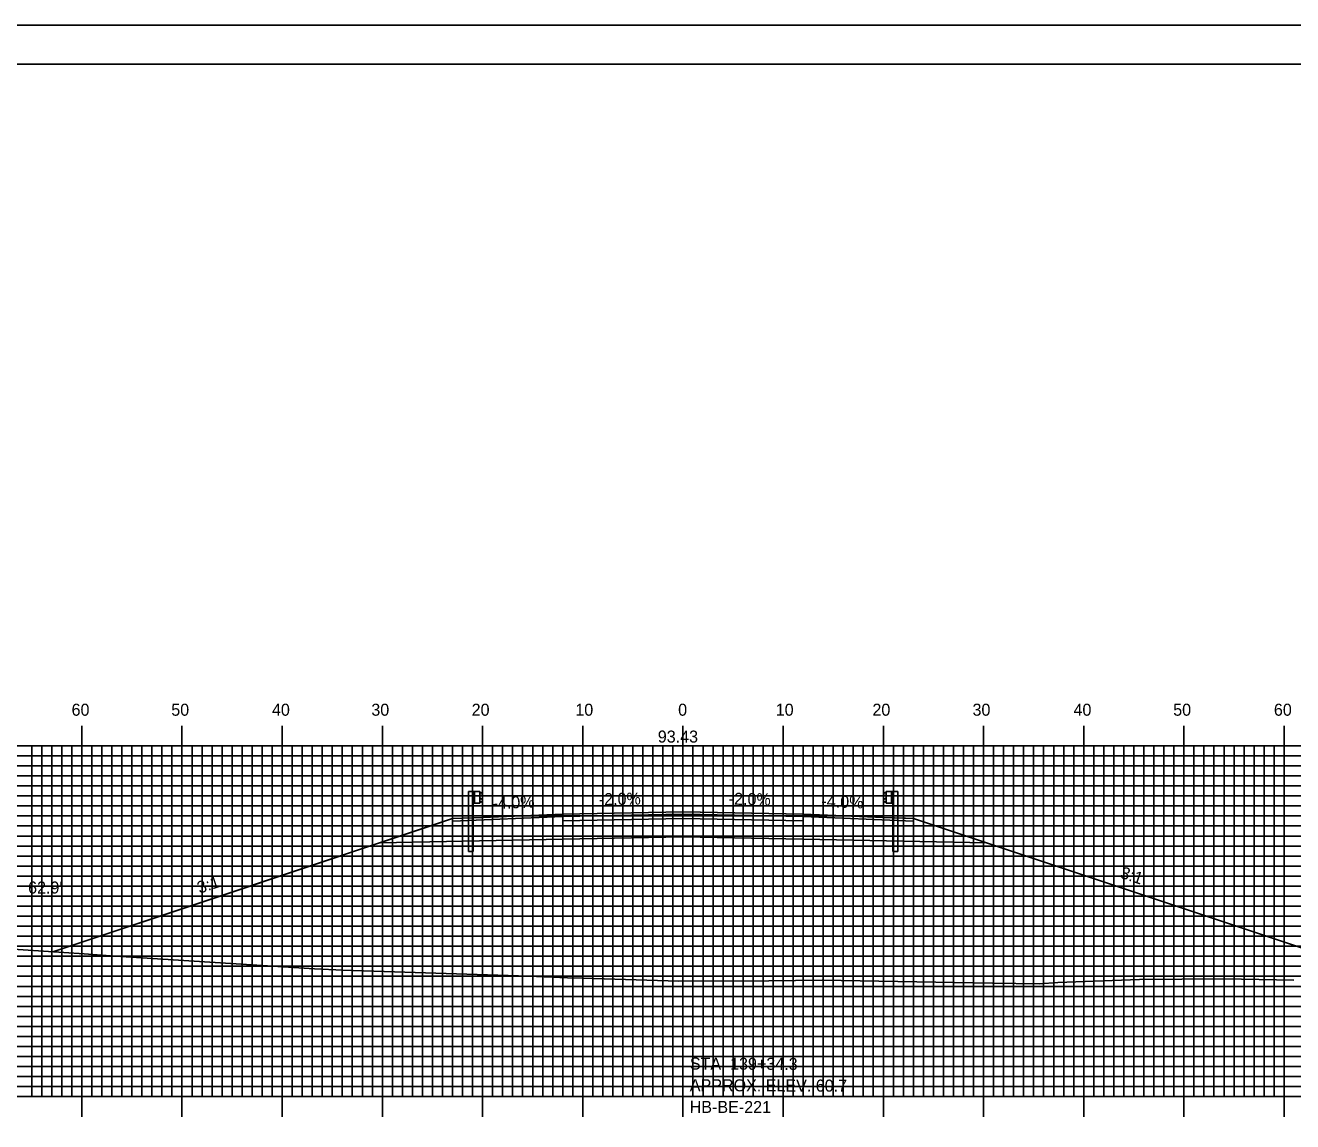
# Model space of a CAD drawing. Extents: x 1775957 to 1776301, y 442591 to 442811.
# Drawn here: x 1776057.6 to 1776184.1, y 442701.2 to 442810.5 of the extents above; entities that cross this region are included whole.
import ezdxf

# ---------------------------------------------------------------- set-up
doc = ezdxf.new("R2010")
doc.units = 0
for name, color, linetype in [('ANNOTATION', 7, 'Continuous'), ('BORDER', 7, 'Continuous'), ('BORING - NO REFUSAL', 7, 'Continuous'), ('D_Guardrail_Beam_Lt', 7, 'Continuous'), ('D_Guardrail_Beam_Rt', 7, 'Continuous'), ('D_Roadway_Centerline', 7, 'Continuous'), ('D_Roadway_Centerline_Text', 7, 'Continuous'), ('D_Roadway_Edge_Shoulder', 7, 'Continuous'), ('D_Roadway_Edge_TW', 7, 'Continuous'), ('D_Roadway_Pavement', 7, 'Continuous'), ('D_Roadway_SlopeLines', 7, 'Continuous'), ('D_Roadway_SubGrade', 7, 'Continuous'), ('D_Text_Standard', 7, 'Continuous'), ('H_V ANNOTATION', 7, 'Continuous'), ('MAJOR', 7, 'Continuous'), ('MINOR', 7, 'Continuous'), ('PLOT BOUNDARY', 7, 'Continuous'), ('S_Roadway_Centerline', 7, 'Continuous')]:
    doc.layers.add(name, color=color, linetype=linetype)

msp = doc.modelspace()

# ---------------------------------------------------------------- linework, layer by layer
at = {"layer": 'BORDER'}
msp.add_lwpolyline([(1775973.62, 442596.67), (1776293.62, 442596.67), (1776293.62, 442806.67), (1775973.62, 442806.67)], close=True, dxfattribs=at)
at = {"layer": 'D_Guardrail_Beam_Lt'}
for p, q in [((1776101.8, 442734.12), (1776101.8, 442728.12)), ((1776102.27, 442734.12), (1776101.8, 442734.12)), ((1776102.95, 442734.12), (1776102.27, 442734.12)), ((1776102.27, 442734.12), (1776102.27, 442732.95)), ((1776102.27, 442732.95), (1776102.95, 442732.95)), ((1776102.29, 442728.12), (1776102.29, 442732.95)), ((1776102.33, 442734.12), (1776102.33, 442732.95)), ((1776102.43, 442734.12), (1776102.43, 442732.95)), ((1776102.95, 442732.95), (1776102.95, 442734.12)), ((1776102.95, 442734.03), (1776103.03, 442734.02)), ((1776103.03, 442733.05), (1776102.95, 442733.03)), ((1776102.96, 442733.57), (1776102.96, 442733.5)), ((1776103.19, 442733.77), (1776102.99, 442733.63)), ((1776102.99, 442733.43), (1776103.19, 442733.3)), ((1776103.04, 442734.01), (1776103.19, 442733.91)), ((1776103.19, 442733.16), (1776103.04, 442733.06)), ((1776102.29, 442728.12), (1776101.8, 442728.12))]:
    msp.add_line(p, q, dxfattribs=at)
for centre, major_axis, start_param, end_param in [((1776103.04, 442733.57), (-0.0789, 0), 5.323254, 6.283185), ((1776103.04, 442733.5), (-0.0789, 0), 6.283185, 7.243116), ((1776103.02, 442733.98), (0.0417, 0), 0.959931, 1.376053), ((1776103.02, 442733.09), (0.0417, 0), 4.907132, 5.323254), ((1776103.14, 442733.84), (0.0877, 0), 5.323254, 7.243116), ((1776103.14, 442733.23), (0.0877, 0), 5.323254, 7.243116)]:
    msp.add_ellipse(centre, major_axis=major_axis, ratio=0.995501, start_param=start_param, end_param=end_param, dxfattribs=at)
at = {"layer": 'D_Guardrail_Beam_Rt'}
for p, q in [((1776143.41, 442734.01), (1776143.26, 442733.91)), ((1776143.26, 442733.77), (1776143.46, 442733.63)), ((1776143.46, 442733.43), (1776143.26, 442733.3)), ((1776143.26, 442733.16), (1776143.41, 442733.06)), ((1776143.5, 442734.03), (1776143.42, 442734.02)), ((1776143.42, 442733.05), (1776143.5, 442733.03)), ((1776143.49, 442733.57), (1776143.49, 442733.5)), ((1776143.5, 442734.12), (1776144.18, 442734.12)), ((1776143.5, 442732.95), (1776143.5, 442734.12)), ((1776144.18, 442732.95), (1776143.5, 442732.95)), ((1776144.02, 442734.12), (1776144.02, 442732.95)), ((1776144.12, 442734.12), (1776144.12, 442732.95)), ((1776144.16, 442728.12), (1776144.16, 442732.95)), ((1776144.18, 442734.12), (1776144.65, 442734.12)), ((1776144.18, 442734.12), (1776144.18, 442732.95)), ((1776144.65, 442734.12), (1776144.65, 442728.12)), ((1776144.16, 442728.12), (1776144.65, 442728.12))]:
    msp.add_line(p, q, dxfattribs=at)
for centre, major_axis, start_param, end_param in [((1776143.31, 442733.84), (-0.0877, 0), 5.323254, 7.243116), ((1776143.31, 442733.23), (-0.0877, 0), 5.323254, 7.243116), ((1776143.43, 442733.98), (-0.0417, 0), 4.907132, 5.323254), ((1776143.43, 442733.09), (-0.0417, 0), 0.959931, 1.376053), ((1776143.41, 442733.57), (0.0789, 0), 0, 0.959931), ((1776143.41, 442733.5), (0.0789, 0), 5.323254, 6.283185)]:
    msp.add_ellipse(centre, major_axis=major_axis, ratio=0.995501, start_param=start_param, end_param=end_param, dxfattribs=at)
at = {"layer": 'D_Roadway_Centerline'}
msp.add_lwpolyline([(1776060.32, 442718.11), (1776060.34, 442718.12), (1776077.43, 442723.81), (1776092.93, 442728.98), (1776092.95, 442728.99), (1776092.95, 442728.99), (1776097.86, 442730.63), (1776100.22, 442731.41), (1776103.22, 442731.53), (1776111.22, 442731.85), (1776111.22, 442731.85), (1776111.23, 442731.85), (1776123.22, 442732.09), (1776124.96, 442732.06), (1776135.22, 442731.85), (1776135.23, 442731.85), (1776139.29, 442731.69), (1776143.22, 442731.53), (1776143.22, 442731.53), (1776143.23, 442731.53), (1776145.44, 442731.45), (1776146.22, 442731.41), (1776153.5, 442728.99), (1776153.51, 442728.99), (1776194.92, 442715.18)], dxfattribs=at)
at = {"layer": 'D_Roadway_Edge_Shoulder'}
for points in [[(1776111.22, 442731.85), (1776103.22, 442731.53), (1776103.22, 442731.53), (1776100.22, 442731.41), (1776100.22, 442731.16), (1776111.22, 442731.6)], [(1776135.22, 442731.85), (1776143.22, 442731.53), (1776143.22, 442731.53), (1776146.22, 442731.41), (1776146.22, 442731.16), (1776135.22, 442731.6)]]:
    msp.add_lwpolyline(points, close=True, dxfattribs=at)
at = {"layer": 'D_Roadway_Edge_TW'}
msp.add_lwpolyline([(1776111.22, 442731.6), (1776111.22, 442731.85), (1776123.22, 442732.09), (1776135.22, 442731.85), (1776135.22, 442731.6), (1776123.22, 442731.84)], close=True, dxfattribs=at)
at = {"layer": 'D_Roadway_Pavement'}
msp.add_lwpolyline([(1776111.22, 442731.19), (1776111.22, 442731.6), (1776123.22, 442731.84), (1776135.22, 442731.6), (1776135.22, 442731.19), (1776123.22, 442731.43)], close=True, dxfattribs=at)
for points in [[(1776111.22, 442731.6), (1776111.22, 442731.19)], [(1776135.22, 442731.6), (1776135.22, 442731.19)]]:
    msp.add_lwpolyline(points, dxfattribs=at)
at = {"layer": 'D_Roadway_SlopeLines'}
for points in [[(1776100.22, 442731.41), (1776060.32, 442718.11)], [(1776146.22, 442731.41), (1776194.92, 442715.18)]]:
    msp.add_lwpolyline(points, dxfattribs=at)
at = {"layer": 'D_Roadway_SubGrade'}
for points in [[(1776111.22, 442731.19), (1776111.22, 442731.6), (1776100.22, 442731.16), (1776100.22, 442731.41), (1776092.95, 442728.99), (1776111.22, 442729.35)], [(1776111.22, 442729.35), (1776111.22, 442731.6), (1776111.22, 442731.19), (1776123.22, 442731.43), (1776135.22, 442731.19), (1776135.22, 442731.6), (1776135.22, 442729.35), (1776123.22, 442729.59)], [(1776135.22, 442731.19), (1776135.22, 442731.6), (1776146.22, 442731.16), (1776146.22, 442731.41), (1776153.5, 442728.99), (1776135.22, 442729.35)]]:
    msp.add_lwpolyline(points, close=True, dxfattribs=at)
at = {"layer": 'MAJOR'}
for p, q in [((1776063.22, 442740.67), (1776063.22, 442738.67)), ((1776073.22, 442740.67), (1776073.22, 442738.67)), ((1776083.22, 442740.67), (1776083.22, 442738.67)), ((1776093.22, 442740.67), (1776093.22, 442738.67)), ((1776103.22, 442740.67), (1776103.22, 442738.67)), ((1776113.22, 442740.67), (1776113.22, 442738.67)), ((1776123.22, 442740.67), (1776123.22, 442738.67)), ((1776133.22, 442740.67), (1776133.22, 442738.67)), ((1776143.22, 442740.67), (1776143.22, 442738.67)), ((1776153.22, 442740.67), (1776153.22, 442738.67)), ((1776163.22, 442740.67), (1776163.22, 442738.67)), ((1776173.22, 442740.67), (1776173.22, 442738.67)), ((1776183.22, 442740.67), (1776183.22, 442738.67)), ((1775983.22, 442738.67), (1776263.22, 442738.67)), ((1775983.22, 442738.67), (1776263.22, 442738.67)), ((1776063.22, 442703.67), (1776063.22, 442738.67)), ((1776073.22, 442703.67), (1776073.22, 442738.67)), ((1776083.22, 442703.67), (1776083.22, 442738.67)), ((1776093.22, 442703.67), (1776093.22, 442738.67)), ((1776103.22, 442703.67), (1776103.22, 442738.67)), ((1776113.22, 442703.67), (1776113.22, 442738.67)), ((1776123.22, 442703.67), (1776123.22, 442738.67)), ((1776133.22, 442703.67), (1776133.22, 442738.67)), ((1776143.22, 442703.67), (1776143.22, 442738.67)), ((1776153.22, 442703.67), (1776153.22, 442738.67)), ((1776163.22, 442703.67), (1776163.22, 442738.67)), ((1776173.22, 442703.67), (1776173.22, 442738.67)), ((1776183.22, 442703.67), (1776183.22, 442738.67)), ((1775983.22, 442733.67), (1776263.22, 442733.67)), ((1775983.22, 442728.67), (1776263.22, 442728.67)), ((1775983.22, 442723.67), (1776263.22, 442723.67)), ((1775983.22, 442718.67), (1776263.22, 442718.67)), ((1775983.22, 442713.67), (1776263.22, 442713.67)), ((1775983.22, 442708.67), (1776263.22, 442708.67)), ((1775983.22, 442703.67), (1776263.22, 442703.67)), ((1775983.22, 442703.67), (1776263.22, 442703.67)), ((1776063.22, 442701.66), (1776063.22, 442703.67)), ((1776073.22, 442701.66), (1776073.22, 442703.67)), ((1776083.22, 442701.66), (1776083.22, 442703.67)), ((1776093.22, 442701.66), (1776093.22, 442703.67)), ((1776103.22, 442701.66), (1776103.22, 442703.67)), ((1776113.22, 442701.66), (1776113.22, 442703.67)), ((1776123.22, 442701.66), (1776123.22, 442703.67)), ((1776133.22, 442701.66), (1776133.22, 442703.67)), ((1776143.22, 442701.66), (1776143.22, 442703.67)), ((1776153.22, 442701.66), (1776153.22, 442703.67)), ((1776163.22, 442701.66), (1776163.22, 442703.67)), ((1776173.22, 442701.66), (1776173.22, 442703.67)), ((1776183.22, 442701.66), (1776183.22, 442703.67))]:
    msp.add_line(p, q, dxfattribs=at)
at = {"layer": 'MINOR'}
for p, q in [((1776058.22, 442703.67), (1776058.22, 442738.67)), ((1776059.22, 442703.67), (1776059.22, 442738.67)), ((1776060.22, 442703.67), (1776060.22, 442738.67)), ((1776061.22, 442703.67), (1776061.22, 442738.67)), ((1776062.22, 442703.67), (1776062.22, 442738.67)), ((1776064.22, 442703.67), (1776064.22, 442738.67)), ((1776065.22, 442703.67), (1776065.22, 442738.67)), ((1776066.22, 442703.67), (1776066.22, 442738.67)), ((1776067.22, 442703.67), (1776067.22, 442738.67)), ((1776068.22, 442703.67), (1776068.22, 442738.67)), ((1776069.22, 442703.67), (1776069.22, 442738.67)), ((1776070.22, 442703.67), (1776070.22, 442738.67)), ((1776071.22, 442703.67), (1776071.22, 442738.67)), ((1776072.22, 442703.67), (1776072.22, 442738.67)), ((1776074.22, 442703.67), (1776074.22, 442738.67)), ((1776075.22, 442703.67), (1776075.22, 442738.67)), ((1776076.22, 442703.67), (1776076.22, 442738.67)), ((1776077.22, 442703.67), (1776077.22, 442738.67)), ((1776078.22, 442703.67), (1776078.22, 442738.67)), ((1776079.22, 442703.67), (1776079.22, 442738.67)), ((1776080.22, 442703.67), (1776080.22, 442738.67)), ((1776081.22, 442703.67), (1776081.22, 442738.67)), ((1776082.22, 442703.67), (1776082.22, 442738.67)), ((1776084.22, 442703.67), (1776084.22, 442738.67)), ((1776085.22, 442703.67), (1776085.22, 442738.67)), ((1776086.22, 442703.67), (1776086.22, 442738.67)), ((1776087.22, 442703.67), (1776087.22, 442738.67)), ((1776088.22, 442703.67), (1776088.22, 442738.67)), ((1776089.22, 442703.67), (1776089.22, 442738.67)), ((1776090.22, 442703.67), (1776090.22, 442738.67)), ((1776091.22, 442703.67), (1776091.22, 442738.67)), ((1776092.22, 442703.67), (1776092.22, 442738.67)), ((1776094.22, 442703.67), (1776094.22, 442738.67)), ((1776095.22, 442703.67), (1776095.22, 442738.67)), ((1776096.22, 442703.67), (1776096.22, 442738.67)), ((1776097.22, 442703.67), (1776097.22, 442738.67)), ((1776098.22, 442703.67), (1776098.22, 442738.67)), ((1776099.22, 442703.67), (1776099.22, 442738.67)), ((1776100.22, 442703.67), (1776100.22, 442738.67)), ((1776101.22, 442703.67), (1776101.22, 442738.67)), ((1776102.22, 442703.67), (1776102.22, 442738.67)), ((1776104.22, 442703.67), (1776104.22, 442738.67)), ((1776105.22, 442703.67), (1776105.22, 442738.67)), ((1776106.22, 442703.67), (1776106.22, 442738.67)), ((1776107.22, 442703.67), (1776107.22, 442738.67)), ((1776108.22, 442703.67), (1776108.22, 442738.67)), ((1776109.22, 442703.67), (1776109.22, 442738.67)), ((1776110.22, 442703.67), (1776110.22, 442738.67)), ((1776111.22, 442703.67), (1776111.22, 442738.67)), ((1776112.22, 442703.67), (1776112.22, 442738.67)), ((1776114.22, 442703.67), (1776114.22, 442738.67)), ((1776115.22, 442703.67), (1776115.22, 442738.67)), ((1776116.22, 442703.67), (1776116.22, 442738.67)), ((1776117.22, 442703.67), (1776117.22, 442738.67)), ((1776118.22, 442703.67), (1776118.22, 442738.67)), ((1776119.22, 442703.67), (1776119.22, 442738.67)), ((1776120.22, 442703.67), (1776120.22, 442738.67)), ((1776121.22, 442703.67), (1776121.22, 442738.67)), ((1776122.22, 442703.67), (1776122.22, 442738.67)), ((1776124.22, 442703.67), (1776124.22, 442738.67)), ((1776125.22, 442703.67), (1776125.22, 442738.67)), ((1776126.22, 442703.67), (1776126.22, 442738.67)), ((1776127.22, 442703.67), (1776127.22, 442738.67)), ((1776128.22, 442703.67), (1776128.22, 442738.67)), ((1776129.22, 442703.67), (1776129.22, 442738.67)), ((1776130.22, 442703.67), (1776130.22, 442738.67)), ((1776131.22, 442703.67), (1776131.22, 442738.67)), ((1776132.22, 442703.67), (1776132.22, 442738.67)), ((1776134.22, 442703.67), (1776134.22, 442738.67)), ((1776135.22, 442703.67), (1776135.22, 442738.67)), ((1776136.22, 442703.67), (1776136.22, 442738.67)), ((1776137.22, 442703.67), (1776137.22, 442738.67)), ((1776138.22, 442703.67), (1776138.22, 442738.67)), ((1776139.22, 442703.67), (1776139.22, 442738.67)), ((1776140.22, 442703.67), (1776140.22, 442738.67)), ((1776141.22, 442703.67), (1776141.22, 442738.67)), ((1776142.22, 442703.67), (1776142.22, 442738.67)), ((1776144.22, 442703.67), (1776144.22, 442738.67)), ((1776145.22, 442703.67), (1776145.22, 442738.67)), ((1776146.22, 442703.67), (1776146.22, 442738.67)), ((1776147.22, 442703.67), (1776147.22, 442738.67)), ((1776148.22, 442703.67), (1776148.22, 442738.67)), ((1776149.22, 442703.67), (1776149.22, 442738.67)), ((1776150.22, 442703.67), (1776150.22, 442738.67)), ((1776151.22, 442703.67), (1776151.22, 442738.67)), ((1776152.22, 442703.67), (1776152.22, 442738.67)), ((1776154.22, 442703.67), (1776154.22, 442738.67)), ((1776155.22, 442703.67), (1776155.22, 442738.67)), ((1776156.22, 442703.67), (1776156.22, 442738.67)), ((1776157.22, 442703.67), (1776157.22, 442738.67)), ((1776158.22, 442703.67), (1776158.22, 442738.67)), ((1776159.22, 442703.67), (1776159.22, 442738.67)), ((1776160.22, 442703.67), (1776160.22, 442738.67)), ((1776161.22, 442703.67), (1776161.22, 442738.67)), ((1776162.22, 442703.67), (1776162.22, 442738.67)), ((1776164.22, 442703.67), (1776164.22, 442738.67)), ((1776165.22, 442703.67), (1776165.22, 442738.67)), ((1776166.22, 442703.67), (1776166.22, 442738.67)), ((1776167.22, 442703.67), (1776167.22, 442738.67)), ((1776168.22, 442703.67), (1776168.22, 442738.67)), ((1776169.22, 442703.67), (1776169.22, 442738.67)), ((1776170.22, 442703.67), (1776170.22, 442738.67)), ((1776171.22, 442703.67), (1776171.22, 442738.67)), ((1776172.22, 442703.67), (1776172.22, 442738.67)), ((1776174.22, 442703.67), (1776174.22, 442738.67)), ((1776175.22, 442703.67), (1776175.22, 442738.67)), ((1776176.22, 442703.67), (1776176.22, 442738.67)), ((1776177.22, 442703.67), (1776177.22, 442738.67)), ((1776178.22, 442703.67), (1776178.22, 442738.67)), ((1776179.22, 442703.67), (1776179.22, 442738.67)), ((1776180.22, 442703.67), (1776180.22, 442738.67)), ((1776181.22, 442703.67), (1776181.22, 442738.67)), ((1776182.22, 442703.67), (1776182.22, 442738.67)), ((1775983.22, 442737.67), (1776263.22, 442737.67)), ((1775983.22, 442736.67), (1776263.22, 442736.67)), ((1775983.22, 442735.67), (1776263.22, 442735.67)), ((1775983.22, 442734.67), (1776263.22, 442734.67)), ((1775983.22, 442732.67), (1776263.22, 442732.67)), ((1775983.22, 442731.67), (1776263.22, 442731.67)), ((1775983.22, 442730.67), (1776263.22, 442730.67)), ((1775983.22, 442729.67), (1776263.22, 442729.67)), ((1775983.22, 442727.67), (1776263.22, 442727.67)), ((1775983.22, 442726.67), (1776263.22, 442726.67)), ((1775983.22, 442725.67), (1776263.22, 442725.67)), ((1775983.22, 442724.67), (1776263.22, 442724.67)), ((1775983.22, 442722.67), (1776263.22, 442722.67)), ((1775983.22, 442721.67), (1776263.22, 442721.67)), ((1775983.22, 442720.67), (1776263.22, 442720.67)), ((1775983.22, 442719.67), (1776263.22, 442719.67)), ((1775983.22, 442717.67), (1776263.22, 442717.67)), ((1775983.22, 442716.67), (1776263.22, 442716.67)), ((1775983.22, 442715.67), (1776263.22, 442715.67)), ((1775983.22, 442714.67), (1776263.22, 442714.67)), ((1775983.22, 442712.67), (1776263.22, 442712.67)), ((1775983.22, 442711.67), (1776263.22, 442711.67)), ((1775983.22, 442710.67), (1776263.22, 442710.67)), ((1775983.22, 442709.67), (1776263.22, 442709.67)), ((1775983.22, 442707.67), (1776263.22, 442707.67)), ((1775983.22, 442706.67), (1776263.22, 442706.67)), ((1775983.22, 442705.67), (1776263.22, 442705.67)), ((1775983.22, 442704.67), (1776263.22, 442704.67))]:
    msp.add_line(p, q, dxfattribs=at)
at = {"layer": 'PLOT BOUNDARY'}
msp.add_lwpolyline([(1775957.44, 442590.55), (1776297.44, 442590.55), (1776297.44, 442810.55), (1775957.44, 442810.55)], close=True, dxfattribs=at)
at = {"layer": 'S_Roadway_Centerline'}
msp.add_lwpolyline([(1776053.29, 442718.58), (1776063.47, 442717.9), (1776066.07, 442717.71), (1776086.43, 442716.42), (1776089.28, 442716.3), (1776107.85, 442715.68), (1776111.71, 442715.51), (1776113.24, 442715.48), (1776122.8, 442715.2), (1776131.78, 442715.23), (1776137.11, 442715.29), (1776154.11, 442715), (1776158.81, 442714.91), (1776160.65, 442715.04), (1776168.8, 442715.34), (1776177.22, 442715.41), (1776184.18, 442715.3)], dxfattribs=at)

# ---------------------------------------------------------------- texts
at = {"layer": 'ANNOTATION'}
for s, rotation, p in [('-4.0%', 2.2906, (1776104.24, 442732.34)), ('-2.0%', 1.1458, (1776114.83, 442732.73)), ('-2.0%', 358.8542, (1776127.78, 442732.8)), ('-4.0%', 357.7092, (1776137.02, 442732.58)), ('3:1', 18.4342, (1776074.97, 442723.91)), ('3:1', 341.5658, (1776166.78, 442725.52))]:
    msp.add_text(s, height=1.2, rotation=rotation, dxfattribs=at).set_placement(p)
at = {"layer": 'BORING - NO REFUSAL'}
for s, p in [('STA. 139+34.3', (1776123.91, 442706.37)), ('APPROX. ELEV. 60.7', (1776123.9, 442704.21)), ('HB-BE-221', (1776123.89, 442702.05))]:
    msp.add_text(s, height=1.2, rotation=359.8142, dxfattribs=at).set_placement(p)
at = {"layer": 'D_Roadway_Centerline'}
for s in ['C', 'L']:
    msp.add_text(s, height=0.0146, dxfattribs=at).set_placement((1776123.22, 442732.09))
at = {"layer": 'D_Roadway_Centerline_Text'}
msp.add_text('93.43', height=1.2, dxfattribs=at).set_placement((1776120.71, 442738.99))
at = {"layer": 'D_Text_Standard'}
msp.add_text("62.9'", height=1.2, dxfattribs=at).set_placement((1776057.86, 442723.93))
at = {"layer": 'H_V ANNOTATION'}
for s, p in [('60', (1776062.2, 442741.67)), ('50', (1776072.15, 442741.67)), ('40', (1776082.2, 442741.67)), ('30', (1776092.12, 442741.67)), ('20', (1776102.13, 442741.67)), ('10', (1776112.48, 442741.67)), ('0', (1776122.74, 442741.67)), ('10', (1776132.48, 442741.67)), ('20', (1776142.13, 442741.67)), ('30', (1776152.12, 442741.67)), ('40', (1776162.2, 442741.67)), ('50', (1776172.15, 442741.67)), ('60', (1776182.2, 442741.67))]:
    msp.add_text(s, height=1.2, dxfattribs=at).set_placement(p)

doc.saveas('drawing.dxf')
